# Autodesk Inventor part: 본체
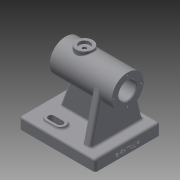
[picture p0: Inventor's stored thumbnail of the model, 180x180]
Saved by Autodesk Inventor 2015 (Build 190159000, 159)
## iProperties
Created: 2022-06
Part Number: 본체
Material: 일반
Document SubType Name: Modeling
Designer: 103-20
Density: 1 g/cm^3
Appearance: 기본값
Author: 103-20
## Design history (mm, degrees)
sketch "스케치1"
  geometry: L1 (0, 0)-(100, 0); L2 (100, 0)-(100, 86); L3 (100, 86)-(0, 86); L4 (0, 86)-(0, 0)
  constraints: 8 end point, 2 parallel, 1 horizontal, 1 perpendicular
  dimensions: "d0" = 100 distance of L2.end L3.end; "d1" = 86 distance of L1.end L2.end
extrude "돌출1" new body sketch "스케치1" distance "d2" = 15; taper "d3" = 0 deg
node "작업 평면1"
sketch "스케치4"
  geometry: L1 (0, 0)-(0, 86) reference; L2 (0, 0)-(-15, 0) reference; L3 (-15, 0)-(-15, 86) reference; L4 (-15, 8)-(-76.814, 22.559); L5 (-15, 78)-(-76.814, 63.441); L6 (0, 0)-(-15, 0) reference; L7 (-15, 0)-(-15, 86) reference; L8 (-15, 86)-(0, 86) reference; L9 (0, 86)-(0, 0) reference; A1 r 21 centre (-72, 43) between (-76.814, 22.559) and (-76.814, 63.441)
  constraints: 4 end point, 2 point on circle, 2 point on line, 2 tangent, 1 centre point
  dimensions: "d12" = 42 diameter of A1; "d13" = 72 distance from line of A1.centre L1; "d14" = 43 distance from line of L2 A1.centre; "d15" = 8 distance of L2.end L4.start; "d16" = 8 distance of L3.end L5.start
extrude "돌출2" join sketch "스케치4" distance "d17" = 10; taper "d18" = 0 deg
sketch "스케치5"
  geometry: L1 (75, 8)-(75, 78) reference; L2 (0, 86)-(0, 0) reference; L3 (75, 48)-(15, 48); L4 (15, 48)-(15, 38); L5 (15, 38)-(75, 38); L6 (75, 38)-(75, 48); L7 (75, 48)-(15, 38); L8 (15, 48)-(75, 38); 3 further points
  constraints: 12 end point, 4 midpoint, 2 parallel, 1 horizontal, 1 perpendicular
  dimensions: "d19" = 43 vertical distance of point (100, 0) point (45, 43); "d20" = 10 distance of L3.end L4.end; "d21" = 15 distance between parallel lines of L2 L4
extrude "돌출3" join sketch "스케치5" distance "d22" = 72; taper "d23" = 0 deg
sketch "스케치6"
  geometry: L1 (0, 0)-(0, 86) reference; L2 (0, 86)-(-15, 86) reference; C1 r 21 at (-72, 43)
  constraints: 1 centre point
  dimensions: "d24" = 42 diameter of C1; "d25" = 43 distance from line of C1.centre L2; "d26" = 72 distance from line of L1 C1.centre
extrude "돌출4" join sketch "스케치6" distance "d27" = 82; taper "d28" = 0 deg
feature "면 기울기1" dims angle "d29" = 20 deg
sketch "스케치7"
  geometry: C1 r 21 at (0, 0) reference; C2 r 11.5 at (0, 0); 1 further point
  constraints: 1 centre point, 1 coincident
  dimensions: "d30" = 23 diameter of C2
extrude "돌출5" cut sketch "스케치7" distance "d31" = 20; taper "d32" = 0 deg
sketch "스케치8"
  geometry: C1 r 21 at (0, 0) reference; C2 r 14.5 at (0, 0); 1 further point
  constraints: 1 centre point, 1 coincident
  dimensions: "d33" = 29 diameter of C2
extrude "돌출6" cut sketch "스케치8" distance "d34" = 62; taper "d35" = 0 deg
sketch "스케치9"
  geometry: C1 r 11.5 at (0, 0) reference; 2 further points
  constraints: 1 horizontal alignment
  dimensions: "d42" = 18 distance of C1.centre point (-18, 0)
hole "구멍1" sketch "스케치9" at (-18, 0) diameter "d43" = 2.459; stored, may be unused: countersink angle "d47" = 90 deg, drill point angle "d49" = 118 deg; dims "d44" = 8, "d45" = 4, "d46" = 2, "d48" = 10
sketch "스케치10"
  geometry: C1 r 14.5 at (0, 0) reference; 2 further points
  constraints: 1 horizontal alignment
  dimensions: "d53" = 18 distance of C1.centre point (18, 0)
hole "구멍2" sketch "스케치10" at (18, 0) diameter "d54" = 2.459; stored, may be unused: countersink angle "d58" = 90 deg, drill point angle "d60" = 118 deg; dims "d55" = 8, "d56" = 4, "d57" = 2, "d59" = 10
node "작업 평면2"
sketch "스케치11"
  geometry: L1 (18, 64)-(18, 22) reference; C1 r 11 at (43, 43); 2 further points
  constraints: 1 centre point, 1 horizontal alignment, 1 midpoint
  dimensions: "d65" = 22 diameter of C1; "d66" = 25 distance from line of L1 C1.centre
extrude "돌출7" join sketch "스케치11" stored distance "d67" = 62; taper "d68" = 0 deg
sketch "스케치12"
  geometry: C1 r 11 at (0, 0) reference; 1 further point
hole "구멍3" sketch "스케치12" at (0, 0) diameter "d69" = 4.917; stored, may be unused: countersink angle "d73" = 90 deg, drill point angle "d75" = 0 deg; dims "d70" = 12, "d71" = 14, "d72" = 4, "d74" = 17.1
fillet "모깎기7" dims "d76" = 1
chamfer "모따기1" distance "d77" = 1; stored, may be unused: second distance "d78" = 2, angle "d79" = 45 deg
sketch "스케치14"
  geometry: L1 (0, 0)-(100, 0) reference; L2 (100, 86)-(0, 86) reference; L3 (0, 86)-(0, 0) reference; L4 (26, 70)-(38, 70); L5 (26, 63)-(38, 63); L6 (38, 77)-(26, 77); L7 (26, 16)-(38, 16); L8 (26, 9)-(38, 9); L9 (38, 23)-(26, 23); A1 r 7 centre (26, 70) between (26, 77) and (26, 63); A2 r 7 centre (38, 70) between (38, 63) and (38, 77); A3 r 7 centre (26, 16) between (26, 23) and (26, 9); A4 r 7 centre (38, 16) between (38, 9) and (38, 23); 2 further points
  constraints: 16 end point, 8 point on circle, 8 tangent, 4 centre point, 3 parallel, 2 midpoint, 1 horizontal
  dimensions: "d83" = 16 distance from line of L1 L7.start; "d84" = 54 distance of L4.start L7.start; "d85" = 12 distance of L4.end L4.start; "d86" = 12 distance of L7.end L7.start; "d87" = 16 distance from line of L2 L4.start; "d88" = 26 distance from line of L3 L4.start; "d92" = 14 distance between parallel lines of L5 L6; "d93" = 14 distance between parallel lines of L8 L9
fillet "모깎기8" dims "d89" = 3
fillet "모깎기9" dims "d90" = 3
fillet "모깎기10" dims "d91" = 3
extrude "돌출8" join sketch "스케치14" distance "d94" = 3; taper "d95" = 0 deg
sketch "스케치15"
  geometry: L1 (26, 70)-(38, 70); L2 (26, 66)-(38, 66); L3 (38, 74)-(26, 74); A1 r 7 centre (38, 70) between (38, 63) and (38, 77) reference; A2 r 7 centre (26, 70) between (26, 77) and (26, 63) reference; A3 r 4 centre (26, 70) between (26, 74) and (26, 66); A4 r 4 centre (38, 70) between (38, 66) and (38, 74); 2 further points
  constraints: 8 end point, 4 point on circle, 4 tangent, 2 centre point, 1 horizontal, 1 midpoint, 1 parallel
  dimensions: "d96" = 8 distance between parallel lines of L2 L3
extrude "돌출9" cut sketch "스케치15" stored distance "d97" = 3; taper "d98" = 0 deg
node "작업 평면3"
fillet "모깎기11" dims "d99" = 3
fillet "모깎기12" dims "d100" = 3
fillet "모깎기13" dims "d101" = 3
fillet "모깎기14" dims "d102" = 3
sketch "스케치16"
  geometry: L1 (0, 0)-(0, 80) reference; 3 further points
  constraints: 1 horizontal alignment, 1 midpoint, 1 other
  dimensions: "d103" = 6 distance from line of L1 point (-6, 40)
feature "엠보싱1" sketch "스케치16" dims "d0" = 100, "d1" = 86, "d104" = 0.5, "d105" = 0
node "솔리드1"
pattern_circular "원형 패턴1" dims angle "d51" = 360 deg
pattern_circular "원형 패턴2" dims angle "d62" = 360 deg
mirror "대칭1"
node "절단 모서리 투영1"
other parameters: "d11" = -15, "d64" = 96
